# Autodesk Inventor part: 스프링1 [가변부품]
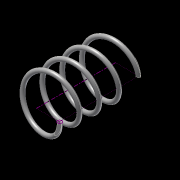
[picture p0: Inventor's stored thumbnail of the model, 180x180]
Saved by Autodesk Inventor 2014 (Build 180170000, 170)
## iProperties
Created: 2015-08
Part Number: 스프링1 [가변부품]
Material: 강철, 연강
Document SubType Name: Modeling
Designer: USER
Mass: 2.84827 g
Surface Area: 9.79852 cm^2
Volume: 0.362375 cm^3
Density: 7.86 g/cm^3
Appearance: 강철
Author: USER
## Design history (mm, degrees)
sketch "스케치1"
  geometry: L1 (0, 0)-(8.25, 0); L2 (8.25, 0)-(8.25, 28); L3 (8.25, 28)-(0, 28); L4 (0, 28)-(0, 0); C1 r 0.75 at (8.25, 0)
  constraints: 8 end point, 2 parallel, 1 centre point, 1 coincident, 1 horizontal, 1 perpendicular
  dimensions: "d0" = 16.5 diameter of L2 L4; "d1" = 28 distance between parallel lines of L1 L3 (derived); "d2" = 1.5 diameter of C1
feature "코일1" sketch "스케치1" pitch "d3" = 10; turns "d5" = 4; dims "d4" = 28 (= d1), "d6" = 0, angle "d7" = 90 deg, angle "d8" = 90 deg, "d9" = 0, "d10" = 0
sketch "스케치2"
  geometry: L1 (-9, 0)-(-7.5, 0) reference; 1 further point
  constraints: 1 horizontal alignment
extrude "돌출1" cut sketch "스케치2" stored distance "d11" = 10; taper "d12" = 0 deg
node "작업 평면1"
sketch "스케치3"
  geometry: L1 (1.5, 0)-(0, 0) reference; 1 further point
  constraints: 1 horizontal alignment
extrude "돌출2" cut sketch "스케치3" stored distance "d13" = 10; taper "d14" = 0 deg
node "솔리드1"
node "절단 모서리 투영1"
node "절단 모서리 투영2"
